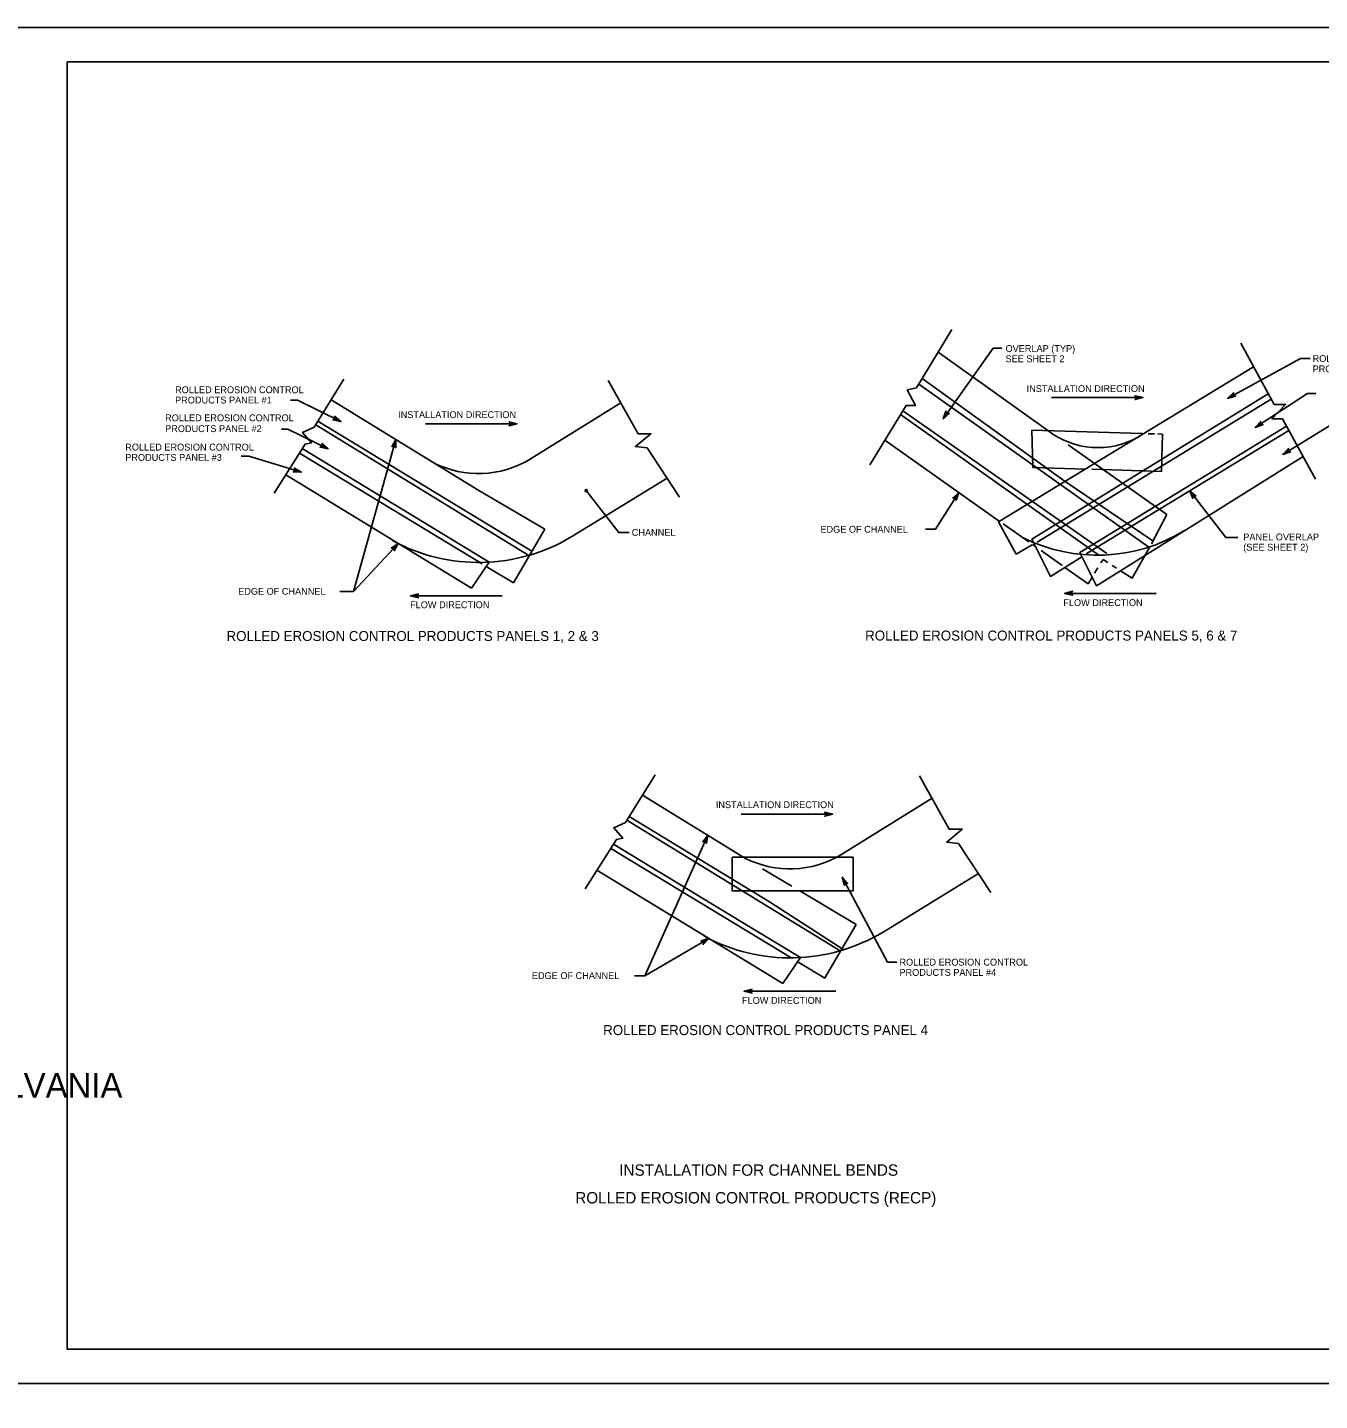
# Model space of a CAD drawing. Extents: x 636462 to 638208, y 299350 to 300538.
# Drawn here: x 637325 to 637891, y 299937 to 300538 of the extents above; entities that cross this region are included whole.
import ezdxf

# ---------------------------------------------------------------- set-up
doc = ezdxf.new("R2010")
doc.units = 0
for name, color, linetype in [('1', 7, 'Continuous'), ('Default', 7, 'Continuous'), ('PLT-BNDY', 7, 'Continuous')]:
    doc.layers.add(name, color=color, linetype=linetype)

msp = doc.modelspace()

# ---------------------------------------------------------------- linework, layer by layer
at = {"layer": '1'}
msp.add_lwpolyline([(638128.91, 299959.45), (638128.91, 300523.45), (637342.91, 300523.45), (637342.91, 299959.45), (638128.91, 299959.45), (638128.91, 299985.81), (637928.91, 299985.81), (637928.91, 300050.49), (638128.91, 300050.49), (638128.91, 300079.45), (637928.91, 300079.45), (637928.91, 299959.45), (638007.72, 299959.45), (638007.72, 299985.81), (638007.72, 299959.45), (638084.72, 299959.45), (638084.72, 299985.81), (638084.72, 299973.49), (638128.91, 299973.49)], dxfattribs=at)
at = {"layer": 'Default'}
for p, q in [((637724.39, 300396.17), (637772.48, 300361.94)), ((637726.51, 300367.05), (637748.44, 300397.96)), ((637748.44, 300397.96), (637752.3, 300397.96)), ((637851.19, 300375.92), (637883.15, 300393.47)), ((637883.15, 300393.47), (637887.37, 300393.47)), ((637717.38, 300384.63), (637780.08, 300339.62)), ((637715.94, 300382.25), (637816.64, 300310.8)), ((637458.55, 300375.38), (637523.24, 300335.57)), ((637585.34, 300373.99), (637545.44, 300349.19)), ((637870.31, 300375.55), (637767.69, 300312.94)), ((637814.14, 300376.29), (637774, 300376.29)), ((637452.71, 300365.98), (637546.42, 300309.02)), ((637707.92, 300368.84), (637794.71, 300307.25)), ((637708.96, 300370.55), (637765.67, 300330.85)), ((637451.72, 300364.39), (637545.06, 300307.17)), ((637539.96, 300364.82), (637499.83, 300364.82)), ((637813.82, 300360.56), (637765.46, 300361.97)), ((637765.46, 300361.97), (637765.88, 300345.67)), ((637877.98, 300361.85), (637789.23, 300307.9)), ((637816.45, 300360.48), (637819.09, 300360.4)), ((637820.64, 300360.36), (637822.7, 300360.3)), ((637445.81, 300353.94), (637501.62, 300320.07)), ((637444.61, 300352.02), (637524.61, 300303.44)), ((637438.57, 300342.47), (637519.94, 300292.88)), ((637765.88, 300345.67), (637788.9, 300344.99)), ((637523.24, 300335.57), (637552.04, 300318.64)), ((637605.62, 300340.96), (637563.91, 300315.39)), ((637818.49, 300313.5), (637780.08, 300339.62)), ((637765.67, 300330.85), (637798.24, 300307.98)), ((637501.62, 300320.07), (637527.77, 300304.2)), ((637552.04, 300318.64), (637538.3, 300295.14)), ((637796.61, 300305.35), (637795.71, 300303.91)), ((637796.61, 300305.35), (637798.64, 300304.05)), ((637527.77, 300304.2), (637519.94, 300292.88)), ((637526.46, 300302.32), (637538.3, 300295.14)), ((637794.37, 300301.75), (637792.9, 300299.38)), ((637800.63, 300302.77), (637802.52, 300301.55)), ((637468.23, 300291.3), (637462.23, 300291.3)), ((637493.2, 300289.41), (637533.33, 300289.41)), ((637779.8, 300290.55), (637819.93, 300290.55)), ((637594.91, 300202.18), (637639.98, 300174.44)), ((637721.7, 300200.79), (637681.81, 300175.99)), ((637588.08, 300191.2), (637681.42, 300133.97)), ((637589.07, 300192.78), (637651.3, 300154.96)), ((637678.19, 300193.82), (637638.06, 300193.82)), ((637580.97, 300178.83), (637660.23, 300130.7)), ((637582.18, 300180.74), (637637.99, 300146.87)), ((637574.93, 300169.27), (637656.31, 300119.69)), ((637660.28, 300162.28), (637647.49, 300169.94)), ((637741.99, 300167.76), (637700.27, 300142.19)), ((637650.54, 300155.42), (637683.01, 300134.45)), ((637688.41, 300145.44), (637663.74, 300160.22)), ((637637.99, 300146.87), (637664.13, 300131)), ((637688.41, 300145.44), (637674.64, 300121.89)), ((637664.13, 300131), (637656.31, 300119.69)), ((637662.68, 300129.21), (637674.71, 300121.91)), ((637595.95, 300123.01), (637591.35, 300123.01)), ((637639.37, 300116.26), (637679.5, 300116.26))]:
    msp.add_line(p, q, dxfattribs=at)
for points in [[(637730.41, 300406.08), (637714.93, 300380.59), (637710.83, 300379.68), (637714.47, 300372.85), (637710.38, 300372.85), (637694.44, 300346.9)], [(637856.96, 300400.16), (637871.53, 300373.31), (637876.54, 300373.31), (637870.62, 300366.93), (637875.17, 300366.93), (637889.74, 300340.53)], [(637862.58, 300389.81), (637750.89, 300321.86), (637758.63, 300307.75), (637765.55, 300311.82)], [(637464.1, 300384.31), (637451.05, 300363.32), (637445.94, 300361.05), (637449.92, 300356.51), (637447.08, 300355.94), (637433.46, 300334.38)], [(637579.86, 300383.75), (637592.91, 300360.48), (637598.59, 300360.48), (637591.78, 300354.81), (637596.89, 300354.24), (637611.07, 300332.68)], [(637869, 300377.97), (637765.46, 300314.35), (637773.65, 300297.96), (637787.29, 300306.56)], [(637810.9, 300376.93), (637810.63, 300377.15), (637814.14, 300376.29), (637810.9, 300376.93), (637811.1, 300376.55), (637814.14, 300376.29), (637811.11, 300376.03), (637810.92, 300375.66), (637814.14, 300376.29), (637810.64, 300375.4), (637810.92, 300375.66)], [(637854.32, 300376.95), (637854.66, 300376.88), (637851.19, 300375.92), (637854.32, 300376.95), (637853.96, 300377.18), (637851.19, 300375.92), (637853.7, 300377.63), (637853.68, 300378.05), (637851.19, 300375.92), (637853.8, 300378.41), (637853.68, 300378.05)], [(637863.28, 300363.2), (637886.22, 300378.1), (637889.85, 300378.1)], [(637462.76, 300365.79), (637443.73, 300375.23), (637440.68, 300375.23)], [(637460.15, 300367.79), (637460, 300368.11), (637462.76, 300365.79), (637460.15, 300367.79), (637460.16, 300367.37), (637462.76, 300365.79), (637459.93, 300366.9), (637459.6, 300366.64), (637462.76, 300365.79), (637459.23, 300366.54), (637459.6, 300366.64)], [(637536.72, 300365.46), (637536.46, 300365.69), (637539.96, 300364.82), (637536.72, 300365.46), (637536.92, 300365.09), (637539.96, 300364.82), (637536.93, 300364.57), (637536.75, 300364.19), (637539.96, 300364.82), (637536.46, 300363.94), (637536.75, 300364.19)], [(637728.9, 300369.32), (637729.24, 300369.41), (637726.51, 300367.05), (637728.9, 300369.32), (637728.48, 300369.37), (637726.51, 300367.05), (637728.05, 300369.67), (637727.85, 300370.04), (637726.51, 300367.05), (637727.81, 300370.42), (637727.85, 300370.04)], [(637866.34, 300364.42), (637866.68, 300364.38), (637863.28, 300363.2), (637866.34, 300364.42), (637865.97, 300364.63), (637863.28, 300363.2), (637865.68, 300365.07), (637865.63, 300365.48), (637863.28, 300363.2), (637865.72, 300365.85), (637865.63, 300365.48)], [(637875.37, 300351.41), (637899.55, 300366.3), (637902.88, 300366.3)], [(637457.17, 300353.9), (637439.54, 300362.47), (637436.75, 300362.47)], [(637876.91, 300363.77), (637786.4, 300308.43), (637793.68, 300293.87), (637884.26, 300350.46)], [(637822.7, 300360.3), (637822.29, 300344), (637791.67, 300344.91)], [(637454.55, 300355.9), (637454.41, 300356.21), (637457.17, 300353.9), (637454.55, 300355.9), (637454.56, 300355.47), (637457.17, 300353.9), (637454.34, 300355), (637454.01, 300354.74), (637457.17, 300353.9), (637453.64, 300354.64), (637454.01, 300354.74)], [(637486.87, 300357.95), (637468.23, 300291.3), (637487.78, 300312.4)], [(637485.4, 300355), (637485.11, 300354.8), (637486.87, 300357.95), (637485.4, 300355), (637485.81, 300355.09), (637486.87, 300357.95), (637486.32, 300354.96), (637486.63, 300354.68), (637486.87, 300357.95), (637486.8, 300354.34), (637486.63, 300354.68)], [(637701.01, 300357.59), (637751.12, 300322.24)], [(637817.81, 300312.2), (637824.54, 300325.08), (637781.32, 300355.57)], [(637878.46, 300352.55), (637878.8, 300352.5), (637875.37, 300351.41), (637878.46, 300352.55), (637878.1, 300352.76), (637875.37, 300351.41), (637877.82, 300353.21), (637877.78, 300353.62), (637875.37, 300351.41), (637877.89, 300353.99), (637877.78, 300353.62)], [(637445.47, 300343.59), (637422.43, 300350.58), (637419.06, 300350.58)], [(637442.56, 300345.13), (637442.37, 300345.42), (637445.47, 300343.59), (637442.56, 300345.13), (637442.64, 300344.72), (637445.47, 300343.59), (637442.5, 300344.21), (637442.22, 300343.91), (637445.47, 300343.59), (637441.87, 300343.75), (637442.22, 300343.91)], [(637589.03, 300317.14), (637584.45, 300317.14), (637570.58, 300335.06)], [(637855.62, 300315.02), (637850.45, 300315.02), (637834.67, 300335.52)], [(637836, 300332.51), (637835.97, 300332.16), (637834.67, 300335.52), (637836, 300332.51), (637836.19, 300332.88), (637834.67, 300335.52), (637836.62, 300333.19), (637837.03, 300333.26), (637834.67, 300335.52), (637837.4, 300333.17), (637837.03, 300333.26)], [(637718.88, 300318.67), (637723.19, 300318.67), (637733.41, 300334.73)], [(637731.12, 300332.36), (637730.79, 300332.25), (637733.41, 300334.73), (637731.12, 300332.36), (637731.54, 300332.32), (637733.41, 300334.73), (637731.99, 300332.04), (637732.2, 300331.69), (637733.41, 300334.73), (637732.26, 300331.31), (637732.2, 300331.69)], [(637752.79, 300321.06), (637764.08, 300313.09)], [(637485.12, 300310.45), (637484.78, 300310.4), (637487.78, 300312.4), (637485.12, 300310.45), (637485.53, 300310.34), (637487.78, 300312.4), (637485.92, 300309.99), (637486.07, 300309.6), (637487.78, 300312.4), (637486.07, 300309.22), (637486.07, 300309.6)], [(637765.73, 300311.93), (637767.19, 300310.9)], [(637804.23, 300300.46), (637809.32, 300297.18), (637817.17, 300310.97)], [(637769.5, 300309.27), (637778.77, 300302.73)], [(637779.92, 300301.92), (637790.04, 300294.78), (637791.67, 300297.4)], [(637496.43, 300288.78), (637496.7, 300288.55), (637493.2, 300289.41), (637496.43, 300288.78), (637496.23, 300289.15), (637493.2, 300289.41), (637496.22, 300289.67), (637496.41, 300290.05), (637493.2, 300289.41), (637496.69, 300290.3), (637496.41, 300290.05)], [(637783.03, 300289.92), (637783.3, 300289.69), (637779.8, 300290.55), (637783.03, 300289.92), (637782.84, 300290.29), (637779.8, 300290.55), (637782.83, 300290.81), (637783.01, 300291.19), (637779.8, 300290.55), (637783.29, 300291.44), (637783.01, 300291.19)], [(637600.47, 300211.11), (637587.42, 300190.12), (637582.31, 300187.85), (637586.28, 300183.31), (637583.44, 300182.74), (637569.82, 300161.18)], [(637716.23, 300210.55), (637729.28, 300187.28), (637734.95, 300187.28), (637728.14, 300181.61), (637733.25, 300181.04), (637747.44, 300159.48)], [(637674.96, 300194.45), (637674.69, 300194.68), (637678.19, 300193.82), (637674.96, 300194.45), (637675.15, 300194.08), (637678.19, 300193.82), (637675.16, 300193.56), (637674.98, 300193.18), (637678.19, 300193.82), (637674.69, 300192.93), (637674.98, 300193.18)], [(637623.43, 300184.63), (637595.95, 300123.01), (637623.96, 300139.29)], [(637621.55, 300181.92), (637621.23, 300181.77), (637623.43, 300184.63), (637621.55, 300181.92), (637621.97, 300181.95), (637623.43, 300184.63), (637622.45, 300181.75), (637622.72, 300181.43), (637623.43, 300184.63), (637622.84, 300181.07), (637622.72, 300181.43)], [(637683.33, 300163.01), (637683.26, 300162.67), (637682.4, 300166.17), (637683.33, 300163.01), (637683.57, 300163.36), (637682.4, 300166.17), (637684.03, 300163.6), (637684.45, 300163.62), (637682.4, 300166.17), (637684.8, 300163.48), (637684.45, 300163.62)], [(637682.4, 300166.17), (637702.24, 300128.93), (637706.32, 300128.93)], [(637620.85, 300138.2), (637620.51, 300138.26), (637623.96, 300139.29), (637620.85, 300138.2), (637621.21, 300137.98), (637623.96, 300139.29), (637621.48, 300137.53), (637621.52, 300137.11), (637623.96, 300139.29), (637621.4, 300136.75), (637621.52, 300137.11)], [(637642.6, 300115.62), (637642.87, 300115.4), (637639.37, 300116.26), (637642.6, 300115.62), (637642.41, 300115.99), (637639.37, 300116.26), (637642.4, 300116.52), (637642.58, 300116.89), (637639.37, 300116.26), (637642.87, 300117.15), (637642.58, 300116.89)]]:
    msp.add_lwpolyline(points, dxfattribs=at)
msp.add_lwpolyline([(637634.12, 300174.94), (637687.12, 300174.94), (637687.12, 300160.22), (637634.12, 300160.22)], close=True, dxfattribs=at)
msp.add_circle((637570.26, 300335.47), 0.513, dxfattribs=at)
for centre, radius, start, end in [((637794.36, 300390.32), 35.92, 232.24934, 299.41405), ((637523.12, 300386.58), 43.55, 243.39835, 300.83947), ((637794.14, 300380.36), 73.11, 243.37483, 301.50874), ((637523.12, 300383.18), 79.11, 241.50477, 301.03756), ((637659.48, 300213.38), 43.55, 243.39835, 300.83947), ((637659.48, 300209.98), 79.11, 241.50477, 301.03756)]:
    msp.add_arc(centre, radius, start, end, dxfattribs=at)
at = {"layer": 'PLT-BNDY'}
for points in [[(637302.91, 300538.45), (638143.91, 300538.45), (638143.91, 299944.45), (637302.91, 299944.45)], [(637302.91, 299944.45), (638143.91, 299944.45), (638143.91, 299350.45), (637302.91, 299350.45)]]:
    msp.add_lwpolyline(points, close=True, dxfattribs=at)

# ---------------------------------------------------------------- texts
at = {"layer": '1'}
msp.add_text('COMMONWEALTH OF PENNSYLVANIA', height=10.7834, dxfattribs=at).set_placement((637101.07, 300069.59))
at = {"layer": 'Default'}
for s, p in [('OVERLAP (TYP)', (637753.89, 300396.3)), ('SEE SHEET 2', (637753.89, 300391.81)), ('ROLLED EROSION CONTROL', (637888.42, 300391.88)), ('PRODUCTS PANEL #5', (637888.42, 300387.38)), ('ROLLED EROSION CONTROL', (637390.12, 300378.23)), ('INSTALLATION DIRECTION', (637763.14, 300378.73)), ('PRODUCTS PANEL #1', (637390.12, 300373.73)), ('ROLLED EROSION CONTROL', (637385.75, 300365.94)), ('INSTALLATION DIRECTION', (637487.82, 300367.32)), ('PRODUCTS PANEL #2', (637385.75, 300361.19)), ('ROLLED EROSION CONTROL', (637368.28, 300353.11)), ('PRODUCTS PANEL #3', (637368.28, 300348.61)), ('FLOW DIRECTION', (637493.07, 300284.05)), ('FLOW DIRECTION', (637779.22, 300284.99)), ('INSTALLATION DIRECTION', (637626.99, 300196.46)), ('ROLLED EROSION CONTROL', (637707.43, 300127.49)), ('PRODUCTS PANEL #4', (637707.43, 300122.99)), ('FLOW DIRECTION', (637638.47, 300110.74))]:
    msp.add_text(s, height=2.998, rotation=359.99982, dxfattribs=at).set_placement(p)
for s, height, p in [('CHANNEL', 2.998, (637590.16, 300315.76)), ('EDGE OF CHANNEL', 2.998, (637672.81, 300317.13)), ('(SEE SHEET 2)', 2.998, (637858.04, 300309.27)), ('PANEL OVERLAP', 2.998, (637858.04, 300313.77)), ('EDGE OF CHANNEL', 2.998, (637417.73, 300289.94)), ('ROLLED EROSION CONTROL PRODUCTS PANELS 1, 2 & 3', 4.3721, (637412.64, 300269.68)), ('ROLLED EROSION CONTROL PRODUCTS PANELS 5, 6 & 7', 4.3721, (637692.39, 300269.88)), ('EDGE OF CHANNEL', 2.998, (637546.42, 300121.58)), ('ROLLED EROSION CONTROL PRODUCTS PANEL 4', 4.3721, (637577.63, 300097.04)), ('INSTALLATION FOR CHANNEL BENDS', 4.9967, (637584.68, 300035.42)), ('ROLLED EROSION CONTROL PRODUCTS (RECP)', 4.9967, (637565.42, 300023.28))]:
    msp.add_text(s, height=height, dxfattribs=at).set_placement(p)

doc.saveas('drawing.dxf')
